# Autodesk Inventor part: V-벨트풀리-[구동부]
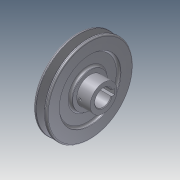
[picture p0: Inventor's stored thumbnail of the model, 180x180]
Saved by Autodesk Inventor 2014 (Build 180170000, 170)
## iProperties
Company: 한국ATC센터
Created: 2014-10
Part Number: V-벨트풀리-[구동부]
Document SubType Name: Modeling
Designer: 한국ATC센터
Density: 7.86 g/cm^3
Material: 강, 연강
Mass: 1515.01 g
Surface Area: 468.125 cm^2
Volume: 192.75 cm^3
Appearance: 강철
Author: KYOUNG IL JANG
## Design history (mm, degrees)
sketch "스케치1"
  geometry: L1 (-20, 0)-(20, 0); L2 (-20, 0)-(-20, 26); L3 (-20, 26)-(-16, 26); L4 (-16, 26)-(-16, 46); L5 (-16, 46)-(-20, 46); L6 (-20, 46)-(-20, 64.5); L7 (-20, 64.5)-(-16.062, 64.5); L8 (-16.062, 64.5)-(-12.001, 52); L9 (-12.001, 52)-(-7.999, 52); L10 (-7.999, 52)-(-3.938, 64.5); L11 (-3.938, 64.5)-(0, 64.5); L12 (0, 64.5)-(0, 46); L13 (0, 46)-(-4, 46); L14 (-4, 46)-(-4, 26); L15 (-4, 26)-(0, 26); L16 (0, 26)-(0, 20); L17 (0, 20)-(20, 20); L18 (20, 20)-(20, 0); L19 (-14.6, 60)-(-5.4, 60); 2 further points
  constraints: 38 end point, 11 parallel, 7 collinear, 3 equal length, 3 perpendicular, 2 point on line, 1 coincident, 1 horizontal, 1 midpoint
  dimensions: "d0" = 40 distance of L1.start L1.end; "d1" = 4.5 distance between parallel lines of L7 L19; "d2" = 8 distance between parallel lines of L9 L19; "d3" = 9.2 distance of L19.start L19.end; "d4" = 36 deg angle of L10 L8; "d5" = 20 distance between parallel lines of L12 L6; "d6" = 120 diameter of L19 L1; "d7" = 4 distance of L2.end L3.end; "d8" = 52 diameter of L3 L1; "d9" = 92 diameter of L5 L1; "d10" = 40 diameter of L17 L1
revolve "회전1" sketch "스케치1" stored, may be unused: angle "d11" = 90 deg
sketch "스케치2"
  geometry: L1 (-4, 11.843)-(-4, 16.5); L2 (-4, 16.5)-(4, 16.5); L3 (4, 16.5)-(4, 11.843); A1 r 12.5 centre (0, 0) between (-4, 11.843) and (4, 11.843); 1 further point
  constraints: 6 end point, 2 parallel, 2 point on circle, 1 centre point, 1 coincident, 1 horizontal, 1 vertical
  dimensions: "d12" = 25 diameter of A1; "d13" = 8 distance of L1.end L2.end; "d14" = 29 dimension on A1 L2
extrude "돌출1" cut sketch "스케치2" stored distance "d15" = 10; taper "d16" = 0 deg
chamfer "모따기1" distance "d17" = 1; stored, may be unused: second distance "d18" = 2, angle "d19" = 45 deg
node "작업 평면1"
sketch "스케치3"
  geometry: L1 (10, -20)-(10, 20) reference; 3 further points
  constraints: 1 horizontal alignment, 1 midpoint
  dimensions: "d20" = 15 distance from line of L1 point (-5, 0)
hole "구멍1" sketch "스케치3" at (-5, 0) diameter "d21" = 4.459; stored, may be unused: countersink angle "d25" = 90 deg, drill point angle "d27" = 118 deg; dims "d22" = 6, "d23" = 4, "d24" = 2, "d26" = 8
fillet "모깎기1" dims "d28" = 3, "d29" = 2, "d30" = 0.5, "d31" = 1
node "솔리드1"
